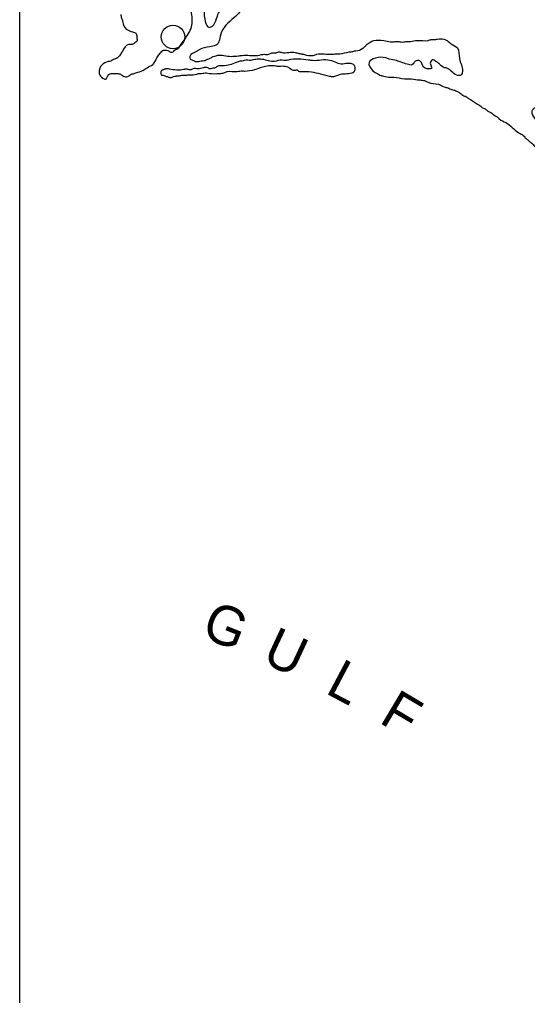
# Model space of a CAD drawing. Extents: x 492225 to 553725, y 1303773 to 1347273.
# Drawn here: x 534984 to 537404, y 1339012 to 1343657 of the extents above; entities that cross this region are included whole.
import ezdxf

# ---------------------------------------------------------------- set-up
doc = ezdxf.new("R2010")
doc.units = 0
for name, color, linetype in [('Level 20', 7, 'Continuous'), ('Level 62', 7, 'Continuous'), ('Level 63', 7, 'Continuous')]:
    doc.layers.add(name, color=color, linetype=linetype)

msp = doc.modelspace()

# ---------------------------------------------------------------- linework, layer by layer
at = {"layer": 'Level 62'}
msp.add_circle((535715.277, 1343573.7555), 55.9017, dxfattribs=at)
at = {"layer": 'Level 63'}
msp.add_lwpolyline([(534984.2995, 1333099.493), (548263.6245, 1333099.498), (548263.6245, 1345038.098), (534984.2995, 1345038.093)], close=True, dxfattribs=at)
for points in [[(535466.562, 1343681.2555), (535470.312, 1343663.7555), (535475.312, 1343648.7555), (535477.812, 1343636.2555), (535485.312, 1343618.7555), (535492.812, 1343611.2555), (535505.312, 1343603.7555), (535527.812, 1343596.2555), (535540.312, 1343588.7555), (535542.812, 1343571.2555), (535542.812, 1343552.5055), (535532.812, 1343545.0055), (535520.312, 1343537.5055), (535505.312, 1343537.5055), (535474.062, 1343505.0055), (535464.062, 1343488.7555), (535446.562, 1343471.2555), (535426.562, 1343463.7555), (535419.062, 1343458.7555), (535406.562, 1343456.2555), (535376.562, 1343440.0055), (535366.562, 1343425.0055), (535364.062, 1343407.5055), (535364.062, 1343397.5055), (535381.562, 1343377.5055), (535394.062, 1343372.5055), (535409.062, 1343395.0055), (535434.062, 1343400.0055), (535444.062, 1343400.0055), (535461.562, 1343397.5055), (535474.062, 1343390.0055), (535494.062, 1343383.7555), (535506.562, 1343388.7555), (535516.562, 1343396.2555), (535526.562, 1343398.7555), (535539.062, 1343403.7555), (535571.562, 1343413.7555), (535591.562, 1343427.5055), (535619.062, 1343442.5055), (535631.562, 1343460.0055), (535639.062, 1343475.0055), (535651.562, 1343492.5055), (535666.562, 1343508.7555), (535684.062, 1343511.2555), (535696.562, 1343506.2555), (535704.062, 1343501.2555), (535719.062, 1343506.2555), (535726.562, 1343513.7555), (535734.062, 1343516.2555), (535749.062, 1343531.2555), (535789.062, 1343590.0055), (535804.062, 1343622.5055), (535804.062, 1343686.2555), (535800.312, 1343736.2555), (535802.812, 1343750.0055), (535812.812, 1343762.5055), (535817.812, 1343767.5055), (535830.312, 1343772.5055), (535845.312, 1343765.0055), (535861.562, 1343735.0055), (535861.562, 1343727.5055), (535864.062, 1343712.5055), (535864.062, 1343681.2555), (535869.062, 1343648.7555), (535889.062, 1343618.7555), (535896.562, 1343621.2555), (535909.062, 1343631.2555), (535926.562, 1343672.5055), (535941.562, 1343700.0055), (535949.062, 1343707.5055), (535976.562, 1343741.2555), (535991.562, 1343751.2555), (536009.062, 1343753.7555), (536024.062, 1343751.2555), (536036.562, 1343731.2555), (536039.062, 1343721.2555), (536034.062, 1343695.0055), (536005.312, 1343665.0055), (535942.812, 1343586.2555), (535932.812, 1343548.7555), (535925.312, 1343537.5055), (535905.312, 1343530.0055), (535890.312, 1343527.5055), (535840.312, 1343512.5055), (535827.812, 1343505.0055), (535795.312, 1343481.2555), (535797.812, 1343468.7555), (535812.812, 1343461.2555), (535832.812, 1343456.2555), (535842.812, 1343458.7555), (535867.812, 1343461.2555)], [(535867.812, 1343461.2555), (535877.812, 1343467.5055), (535892.812, 1343472.5055), (535900.312, 1343477.5055), (535912.812, 1343482.5055), (535942.812, 1343487.5055), (535957.812, 1343485.0055), (536026.562, 1343483.7555), (536044.062, 1343486.2555), (536119.062, 1343486.2555), (536151.562, 1343491.2555), (536171.562, 1343491.2555), (536186.562, 1343497.5055), (536201.562, 1343497.5055), (536219.062, 1343502.5055), (536234.062, 1343500.0055), (536297.812, 1343500.0055), (536315.312, 1343495.0055), (536332.812, 1343492.5055), (536350.312, 1343487.5055), (536392.812, 1343488.7555), (536400.312, 1343491.2555), (536472.812, 1343491.2555), (536497.812, 1343493.7555), (536510.312, 1343493.7555), (536554.062, 1343502.5055), (536571.562, 1343505.0055), (536579.062, 1343507.5055), (536586.562, 1343507.5055), (536619.062, 1343520.0055), (536626.562, 1343525.0055), (536636.562, 1343536.2555), (536654.062, 1343548.7555), (536671.562, 1343556.2555), (536719.062, 1343556.2555), (536751.562, 1343551.2555), (536769.062, 1343551.2555), (536779.062, 1343552.5055), (536801.562, 1343550.0055), (536814.062, 1343550.0055), (536834.062, 1343552.5055), (536846.562, 1343552.5055), (536879.062, 1343557.5055), (536930.312, 1343557.5055), (536945.312, 1343561.2555), (536957.812, 1343561.2555), (536975.312, 1343563.7555), (537005.312, 1343563.7555), (537020.312, 1343556.2555), (537040.312, 1343541.2555), (537070.312, 1343521.2555), (537079.062, 1343471.2555), (537094.062, 1343410.0055), (537086.562, 1343392.5055), (537066.562, 1343392.5055), (537019.062, 1343425.0055), (537009.062, 1343427.5055), (536986.562, 1343442.5055), (536981.562, 1343447.5055), (536967.812, 1343457.5055), (536950.312, 1343465.0055), (536942.812, 1343457.5055), (536942.812, 1343438.7555), (536946.562, 1343423.7555), (536936.562, 1343421.2555), (536920.312, 1343423.7555), (536905.312, 1343436.2555), (536902.812, 1343443.7555), (536892.812, 1343458.7555), (536867.812, 1343456.2555), (536857.812, 1343443.7555), (536810.312, 1343451.2555), (536792.812, 1343456.2555), (536780.312, 1343461.2555), (536745.312, 1343468.7555), (536729.062, 1343473.7555), (536679.062, 1343472.5055), (536649.062, 1343452.5055), (536667.812, 1343412.5055), (536690.312, 1343397.5055), (536700.312, 1343392.5055), (536717.812, 1343387.5055), (536750.312, 1343382.5055), (536767.812, 1343382.5055), (536817.812, 1343375.0055), (536842.812, 1343375.0055), (536879.062, 1343370.0055), (536896.562, 1343368.7555), (536919.062, 1343363.7555), (536934.062, 1343356.2555), (536941.562, 1343353.7555)], [(535697.812, 1343422.5055), (535732.812, 1343417.5055), (535750.312, 1343417.5055), (535765.312, 1343420.0055), (535782.812, 1343421.2555), (535797.812, 1343418.7555), (535812.812, 1343423.7555), (535832.812, 1343423.7555), (535861.562, 1343428.7555), (535879.062, 1343428.7555), (535886.562, 1343423.7555), (535896.562, 1343423.7555), (535906.562, 1343426.2555), (535914.062, 1343426.2555), (535926.562, 1343435.0055), (535944.062, 1343437.5055), (536009.062, 1343450.0055), (536026.562, 1343457.5055), (536036.562, 1343460.0055), (536044.062, 1343460.0055), (536056.562, 1343463.7555), (536086.562, 1343463.7555), (536109.062, 1343468.7555), (536139.062, 1343468.7555), (536199.062, 1343458.7555), (536235.312, 1343465.0055), (536250.312, 1343462.5055), (536265.312, 1343465.0055), (536360.312, 1343465.0055), (536380.312, 1343462.5055), (536462.812, 1343463.7555), (536524.062, 1343446.2555), (536539.062, 1343448.7555), (536556.562, 1343448.7555), (536574.062, 1343443.7555), (536581.562, 1343421.2555), (536576.562, 1343406.2555), (536566.562, 1343401.2555), (536504.062, 1343392.5055), (536484.062, 1343385.0055), (536466.562, 1343385.0055), (536454.062, 1343387.5055), (536362.812, 1343407.5055), (536335.312, 1343407.5055), (536315.312, 1343410.0055), (536307.812, 1343415.0055), (536292.812, 1343413.7555), (536277.812, 1343418.7555), (536267.812, 1343426.2555), (536242.812, 1343433.7555), (536212.812, 1343433.7555), (536192.812, 1343436.2555), (536177.812, 1343436.2555), (536149.062, 1343431.2555), (536056.562, 1343410.0055), (536034.062, 1343410.0055), (536021.562, 1343407.5055), (535971.562, 1343407.5055), (535956.562, 1343401.2555), (535936.562, 1343398.7555), (535889.062, 1343398.7555), (535874.062, 1343401.2555), (535851.562, 1343398.7555), (535841.562, 1343398.7555), (535811.562, 1343392.5055), (535792.812, 1343392.5055), (535775.312, 1343390.0055), (535760.312, 1343390.0055), (535742.812, 1343387.5055), (535730.312, 1343387.5055)], [(535667.812, 1343418.7555), (535666.562, 1343417.5055), (535660.312, 1343413.7555), (535657.812, 1343407.5055), (535657.812, 1343398.7555), (535660.312, 1343392.5055), (535669.062, 1343391.2555), (535682.812, 1343386.2555), (535689.062, 1343385.0055), (535695.312, 1343382.5055), (535711.562, 1343382.5055), (535717.812, 1343385.0055), (535730.312, 1343387.5055)], [(535667.812, 1343418.7555), (535674.062, 1343420.0055), (535680.312, 1343422.5055), (535686.562, 1343423.7555), (535697.812, 1343422.5055)], [(536941.562, 1343353.7555), (536991.562, 1343343.7555), (537006.562, 1343336.2555), (537024.062, 1343331.2555), (537042.812, 1343323.7555), (537052.812, 1343321.2555), (537070.312, 1343313.7555), (537082.812, 1343306.2555), (537100.312, 1343293.7555), (537107.812, 1343291.2555), (537122.812, 1343281.2555), (537132.812, 1343276.2555), (537150.312, 1343263.7555), (537171.562, 1343251.2555), (537181.562, 1343243.7555), (537186.562, 1343238.7555), (537201.562, 1343231.2555), (537214.062, 1343221.2555), (537229.062, 1343213.7555), (537249.062, 1343198.7555), (537261.562, 1343191.2555), (537269.062, 1343183.7555), (537300.312, 1343166.2555), (537360.312, 1343118.7555), (537377.812, 1343108.7555), (537387.812, 1343101.2555), (537392.812, 1343093.7555), (537402.812, 1343086.2555), (537407.812, 1343081.2555), (537424.062, 1343068.7555), (537436.562, 1343053.7555), (537446.562, 1343046.2555), (537471.562, 1343018.7555), (537486.562, 1343006.2555), (537494.062, 1343001.2555), (537506.562, 1342988.7555), (537527.812, 1342973.7555), (537540.312, 1342968.7555), (537555.312, 1342966.2555), (537570.312, 1342971.2555), (537577.812, 1342976.2555), (537582.812, 1342996.2555), (537582.812, 1343008.7555), (537576.562, 1343026.2555), (537569.062, 1343040.0055), (537564.062, 1343047.5055), (537559.062, 1343060.0055), (537549.062, 1343075.0055), (537544.062, 1343087.5055), (537536.562, 1343127.5055), (537510.312, 1343145.0055), (537490.312, 1343152.5055), (537485.312, 1343157.5055), (537470.312, 1343162.5055), (537460.312, 1343170.0055), (537452.812, 1343172.5055), (537440.312, 1343185.0055), (537425.312, 1343217.5055), (537432.812, 1343232.5055), (537442.812, 1343238.7555), (537455.312, 1343238.7555), (537472.812, 1343236.2555), (537482.812, 1343231.2555), (537507.812, 1343223.7555), (537525.312, 1343223.7555), (537535.312, 1343221.2555), (537555.312, 1343221.2555), (537567.812, 1343216.2555), (537585.312, 1343198.7555), (537601.562, 1343188.7555), (537616.562, 1343188.7555), (537639.062, 1343198.7555), (537691.562, 1343217.5055), (537699.062, 1343217.5055), (537714.062, 1343220.0055), (537729.062, 1343220.0055), (537749.062, 1343215.0055), (537761.562, 1343207.5055), (537779.062, 1343215.0055), (537794.062, 1343226.2555), (537809.062, 1343218.7555), (537824.062, 1343195.0055), (537826.562, 1343187.5055), (537831.562, 1343182.5055)]]:
    msp.add_spline(points, degree=3, dxfattribs=at)

# ---------------------------------------------------------------- texts
at = {"layer": 'Level 20'}
for s, height, rotation, p in [('G', 187.5, 337.931514, (535842.6745, 1340721.848)), ('U', 187.5, 335.0429281, (536132.6745, 1340600.598)), ('L', 187.4992, 332.1543422, (536435.1745, 1340453.098)), ('F', 187.4992, 329.2657563, (536691.4245, 1340313.098))]:
    msp.add_text(s, height=height, rotation=rotation, dxfattribs=at).set_placement(p)

doc.saveas('drawing.dxf')
